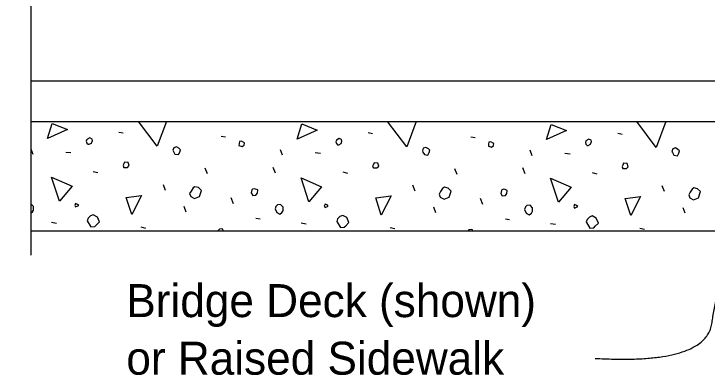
# Model space of a CAD drawing. Extents: x 110698 to 110915, y 110390 to 110472.
# Drawn here: x 110873.339 to 110877.573, y 110456.729 to 110458.938 of the extents above; entities that cross this region are included whole.
import ezdxf

# ---------------------------------------------------------------- set-up
doc = ezdxf.new("R2010")
doc.units = 0
for name, color, linetype in [('PlotBorder_dp', 7, 'Continuous'), ('SheetBorder_dp', 7, 'Continuous'), ('SheetLines_dp', 7, 'Continuous'), ('SupstrConc_h', 7, 'Continuous')]:
    doc.layers.add(name, color=color, linetype=linetype)

msp = doc.modelspace()

# ---------------------------------------------------------------- linework, layer by layer
at = {"layer": 'PlotBorder_dp'}
msp.add_lwpolyline([(110873.4426, 110460.9454), (110873.4426, 110459.0946), (110873.5459, 110459.0946), (110873.4426, 110459.0496), (110873.3392, 110459.0046), (110873.4426, 110459.0046), (110873.4426, 110457.4621)], dxfattribs=at)
msp.add_open_spline([(110876.8897, 110456.8315), (110877.5655, 110456.792), (110877.6393, 110457.2993), (110877.8284, 110458.0281)], degree=2, dxfattribs=at)
at = {"layer": 'SheetBorder_dp'}
for p, q in [((110873.9798, 110458.2151), (110874.0063, 110458.2098)), ((110875.5036, 110458.2115), (110875.5302, 110458.2062)), ((110877.0275, 110458.208), (110877.054, 110458.2027)), ((110874.6056, 110458.1903), (110874.6321, 110458.185)), ((110876.1294, 110458.1868), (110876.1559, 110458.1815)), ((110873.4566, 110458.0772), (110873.4442, 110458.1108)), ((110873.6563, 110458.0931), (110873.6881, 110458.0896)), ((110874.9804, 110458.0736), (110874.968, 110458.1072)), ((110875.1801, 110458.0896), (110875.212, 110458.086)), ((110876.5042, 110458.0701), (110876.4918, 110458.1037)), ((110876.7039, 110458.086), (110876.7358, 110458.0825)), ((110874.5225, 110457.9587), (110874.5084, 110457.9941)), ((110874.938, 110457.964), (110874.9238, 110457.9994)), ((110876.0463, 110457.9552), (110876.0322, 110457.9906)), ((110876.4618, 110457.9605), (110876.4476, 110457.9959)), ((110873.8243, 110457.9746), (110873.8525, 110457.9676)), ((110875.3481, 110457.9711), (110875.3764, 110457.964)), ((110876.8719, 110457.9676), (110876.9002, 110457.9605)), ((110874.2662, 110457.858), (110874.2521, 110457.8933)), ((110875.79, 110457.8544), (110875.7759, 110457.8898)), ((110877.3138, 110457.8509), (110877.2997, 110457.8863)), ((110874.6799, 110457.7767), (110874.6657, 110457.812)), ((110876.2037, 110457.7731), (110876.1895, 110457.8085)), ((110874.3917, 110457.7254), (110874.3793, 110457.759)), ((110875.9155, 110457.7219), (110875.9032, 110457.7554)), ((110877.4393, 110457.7183), (110877.427, 110457.7519)), ((110874.8177, 110457.6883), (110874.8425, 110457.6847)), ((110873.5697, 110457.6635), (110873.5998, 110457.6582)), ((110875.0935, 110457.66), (110875.1236, 110457.6547)), ((110876.3416, 110457.6847), (110876.3663, 110457.6812)), ((110876.6173, 110457.6565), (110876.6474, 110457.6511)), ((110874.1142, 110457.6352), (110874.1425, 110457.6282)), ((110875.638, 110457.6317), (110875.6663, 110457.6246)), ((110877.1618, 110457.6282), (110877.1901, 110457.6211))]:
    msp.add_line(p, q, dxfattribs=at)
for points in [[(110874.2149, 110458.1284), (110874.1007, 110458.2787)], [(110874.2711, 110458.2787), (110874.2149, 110458.1284)], [(110875.7387, 110458.1249), (110875.6219, 110458.2787)], [(110875.7962, 110458.2787), (110875.7387, 110458.1249)], [(110877.2626, 110458.1214), (110877.143, 110458.2787)], [(110877.3214, 110458.2787), (110877.2626, 110458.1214)], [(110873.5449, 110458.1762), (110873.5732, 110458.2681), (110873.6669, 110458.231), (110873.5449, 110458.1762)], [(110875.0688, 110458.1726), (110875.097, 110458.2646), (110875.1907, 110458.2274), (110875.0688, 110458.1726)], [(110876.5926, 110458.1691), (110876.6209, 110458.261), (110876.7146, 110458.2239), (110876.5926, 110458.1691)], [(110873.7924, 110458.1408), (110873.7995, 110458.1408), (110873.8137, 110458.1479), (110873.819, 110458.1638), (110873.8172, 110458.1726), (110873.803, 110458.1797), (110873.7854, 110458.1691), (110873.7818, 110458.1585), (110873.7854, 110458.1479), (110873.7924, 110458.1408)], [(110874.7134, 110458.132), (110874.7329, 110458.1267), (110874.7453, 110458.1355), (110874.747, 110458.1479), (110874.7435, 110458.1514), (110874.7294, 110458.1585), (110874.717, 110458.1567), (110874.7152, 110458.1444), (110874.7134, 110458.132)], [(110875.3163, 110458.1373), (110875.3233, 110458.1373), (110875.3375, 110458.1444), (110875.3428, 110458.1603), (110875.341, 110458.1691), (110875.3269, 110458.1762), (110875.3092, 110458.1656), (110875.3056, 110458.155), (110875.3092, 110458.1444), (110875.3163, 110458.1373)], [(110876.2373, 110458.1284), (110876.2567, 110458.1231), (110876.2691, 110458.132), (110876.2708, 110458.1444), (110876.2673, 110458.1479), (110876.2532, 110458.155), (110876.2408, 110458.1532), (110876.239, 110458.1408), (110876.2373, 110458.1284)], [(110876.8401, 110458.1337), (110876.8471, 110458.1337), (110876.8613, 110458.1408), (110876.8666, 110458.1567), (110876.8648, 110458.1656), (110876.8507, 110458.1726), (110876.833, 110458.162), (110876.8295, 110458.1514), (110876.833, 110458.1408), (110876.8401, 110458.1337)], [(110874.3139, 110458.0966), (110874.3228, 110458.0807), (110874.344, 110458.0772), (110874.3528, 110458.0931), (110874.3564, 110458.1072), (110874.3475, 110458.1161), (110874.3316, 110458.1249), (110874.3157, 110458.1196), (110874.3104, 110458.1037), (110874.3139, 110458.0966)], [(110875.8377, 110458.0931), (110875.8466, 110458.0772), (110875.8678, 110458.0736), (110875.8766, 110458.0896), (110875.8802, 110458.1037), (110875.8713, 110458.1125), (110875.8554, 110458.1214), (110875.8395, 110458.1161), (110875.8342, 110458.1002), (110875.8377, 110458.0931)], [(110877.3616, 110458.0896), (110877.3704, 110458.0736), (110877.3916, 110458.0701), (110877.4004, 110458.086), (110877.404, 110458.1002), (110877.3951, 110458.109), (110877.3792, 110458.1178), (110877.3633, 110458.1125), (110877.358, 110458.0966), (110877.3616, 110458.0896)], [(110874.0116, 110457.9994), (110874.0329, 110457.9994), (110874.0435, 110458.01), (110874.0382, 110458.0295), (110874.0152, 110458.0312), (110874.0116, 110458.0206), (110874.0063, 110458.0118), (110874.0116, 110457.9994), (110874.0081, 110458.0029)], [(110875.5355, 110457.9959), (110875.5567, 110457.9959), (110875.5673, 110458.0065), (110875.562, 110458.0259), (110875.539, 110458.0277), (110875.5355, 110458.0171), (110875.5302, 110458.0082), (110875.5355, 110457.9959), (110875.5319, 110457.9994)], [(110877.0593, 110457.9923), (110877.0805, 110457.9923), (110877.0911, 110458.0029), (110877.0858, 110458.0224), (110877.0628, 110458.0241), (110877.0593, 110458.0135), (110877.054, 110458.0047), (110877.0593, 110457.9923), (110877.0557, 110457.9959)], [(110873.6174, 110457.7926), (110873.5697, 110457.9393), (110873.6952, 110457.8845), (110873.6174, 110457.7926)], [(110875.1412, 110457.789), (110875.0935, 110457.9358), (110875.219, 110457.881), (110875.1412, 110457.789)], [(110876.6651, 110457.7855), (110876.6173, 110457.9322), (110876.7428, 110457.8774), (110876.6651, 110457.7855)], [(110874.42, 110457.8209), (110874.443, 110457.8085), (110874.473, 110457.8209), (110874.4854, 110457.858), (110874.4677, 110457.8757), (110874.4447, 110457.881), (110874.4341, 110457.8739), (110874.4218, 110457.8544), (110874.4129, 110457.8385), (110874.42, 110457.8209)], [(110874.7895, 110457.8438), (110874.7983, 110457.8279), (110874.8177, 110457.8297), (110874.8266, 110457.8421), (110874.8283, 110457.8615), (110874.816, 110457.8668), (110874.8071, 110457.8686), (110874.7965, 110457.865), (110874.793, 110457.8615), (110874.7895, 110457.8438)], [(110875.9438, 110457.8173), (110875.9668, 110457.8049), (110875.9968, 110457.8173), (110876.0092, 110457.8544), (110875.9915, 110457.8721), (110875.9686, 110457.8774), (110875.958, 110457.8704), (110875.9456, 110457.8509), (110875.9367, 110457.835), (110875.9438, 110457.8173)], [(110876.3133, 110457.8403), (110876.3221, 110457.8244), (110876.3416, 110457.8262), (110876.3504, 110457.8385), (110876.3522, 110457.858), (110876.3398, 110457.8633), (110876.331, 110457.865), (110876.3203, 110457.8615), (110876.3168, 110457.858), (110876.3133, 110457.8403)], [(110877.4676, 110457.8138), (110877.4906, 110457.8014), (110877.5207, 110457.8138), (110877.533, 110457.8509), (110877.5154, 110457.8686), (110877.4924, 110457.8739), (110877.4818, 110457.8668), (110877.4694, 110457.8474), (110877.4606, 110457.8315), (110877.4676, 110457.8138)], [(110874.0594, 110457.7113), (110874.0258, 110457.8156), (110874.1195, 110457.8279), (110874.0594, 110457.7113)], [(110875.5832, 110457.7077), (110875.5496, 110457.812), (110875.6433, 110457.8244), (110875.5832, 110457.7077)], [(110877.107, 110457.7042), (110877.0734, 110457.8085), (110877.1671, 110457.8209), (110877.107, 110457.7042)], [(110873.4424, 110457.7192), (110873.453, 110457.7272), (110873.4601, 110457.7378), (110873.4601, 110457.759), (110873.4442, 110457.7749), (110873.4424, 110457.7747)], [(110873.7164, 110457.7572), (110873.7359, 110457.7661), (110873.7288, 110457.7731), (110873.7164, 110457.7784), (110873.7111, 110457.7661), (110873.7164, 110457.7572)], [(110874.9344, 110457.7448), (110874.945, 110457.7236), (110874.9627, 110457.713), (110874.9768, 110457.7236), (110874.9839, 110457.7342), (110874.9839, 110457.7554), (110874.968, 110457.7714), (110874.9486, 110457.7696), (110874.9397, 110457.7607), (110874.9344, 110457.7448)], [(110875.2402, 110457.7537), (110875.2597, 110457.7625), (110875.2526, 110457.7696), (110875.2402, 110457.7749), (110875.2349, 110457.7625), (110875.2402, 110457.7537)], [(110876.7641, 110457.7501), (110876.7835, 110457.759), (110876.7764, 110457.7661), (110876.7641, 110457.7714), (110876.7588, 110457.759), (110876.7641, 110457.7501)], [(110876.4582, 110457.7413), (110876.4688, 110457.7201), (110876.4865, 110457.7095), (110876.5007, 110457.7201), (110876.5077, 110457.7307), (110876.5077, 110457.7519), (110876.4918, 110457.7678), (110876.4724, 110457.7661), (110876.4635, 110457.7572), (110876.4582, 110457.7413)], [(110873.7871, 110457.6724), (110873.8101, 110457.6352), (110873.8331, 110457.637), (110873.8419, 110457.6458), (110873.8614, 110457.6653), (110873.849, 110457.6953), (110873.8243, 110457.7095), (110873.8066, 110457.7024), (110873.7924, 110457.6883), (110873.7871, 110457.6724)], [(110875.3109, 110457.6688), (110875.3339, 110457.6317), (110875.3569, 110457.6335), (110875.3657, 110457.6423), (110875.3852, 110457.6618), (110875.3728, 110457.6918), (110875.3481, 110457.7059), (110875.3304, 110457.6989), (110875.3163, 110457.6847), (110875.3109, 110457.6688)], [(110876.8348, 110457.6653), (110876.8577, 110457.6282), (110876.8807, 110457.6299), (110876.8896, 110457.6388), (110876.909, 110457.6582), (110876.8966, 110457.6883), (110876.8719, 110457.7024), (110876.8542, 110457.6953), (110876.8401, 110457.6812), (110876.8348, 110457.6653)], [(110874.618, 110457.612), (110874.6162, 110457.6211), (110874.6074, 110457.6229), (110874.595, 110457.6211), (110874.5859, 110457.612)], [(110876.1411, 110457.612), (110876.14, 110457.6176), (110876.1312, 110457.6193), (110876.1188, 110457.6176), (110876.1133, 110457.612)]]:
    msp.add_lwpolyline(points, dxfattribs=at)
at = {"layer": 'SheetLines_dp'}
for p, q in [((110873.4424, 110458.2787), (110896.2163, 110458.2787)), ((110873.4424, 110457.612), (110896.2163, 110457.612))]:
    msp.add_line(p, q, dxfattribs=at)
at = {"layer": 'SupstrConc_h'}
msp.add_line((110873.4424, 110458.5287), (110896.2163, 110458.5287), dxfattribs=at)

# ---------------------------------------------------------------- texts
at = {"layer": 'PlotBorder_dp'}
for s, p in [('Bridge Deck (shown)', (110874.0261, 110457.0836)), ('or Raised Sidewalk', (110874.0261, 110456.7316))]:
    msp.add_text(s, height=0.2016, dxfattribs=at).set_placement(p)

doc.saveas('drawing.dxf')
